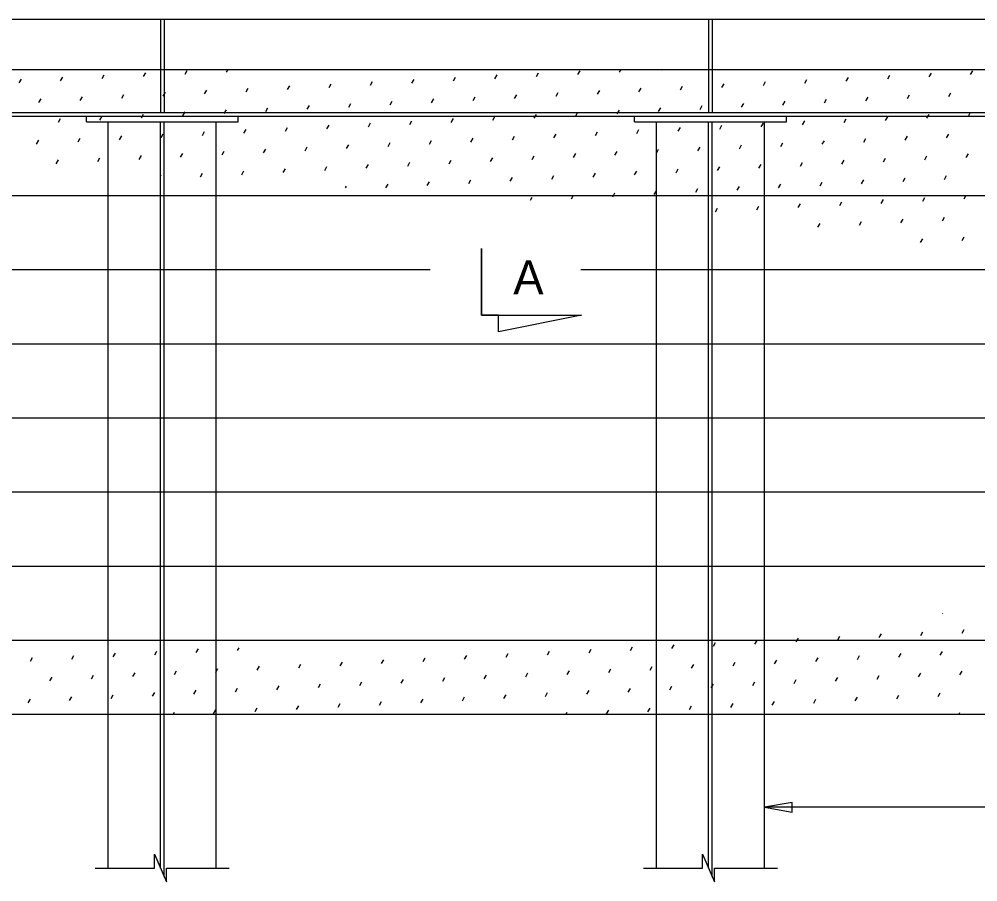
# Model space of a CAD drawing. Extents: x 0 to 61.6, y 0 to 38.9.
# Drawn here: x 30.2 to 40.98, y 14.06 to 23.77 of the extents above; entities that cross this region are included whole.
import ezdxf

# ---------------------------------------------------------------- set-up
doc = ezdxf.new("R2010")
doc.units = 0
for name, color, linetype in [('Dimension', 7, 'Continuous'), ('GroundLines', 7, 'Continuous'), ('SteelMisc', 7, 'Continuous'), ('SteelMisc_h', 7, 'Continuous'), ('Symbols', 7, 'Continuous'), ('TextStructures', 7, 'Continuous'), ('Wood', 7, 'Continuous'), ('Wood_h', 7, 'Continuous')]:
    doc.layers.add(name, color=color, linetype=linetype)

msp = doc.modelspace()

# ---------------------------------------------------------------- linework, layer by layer
at = {"layer": 'Dimension'}
for p, q in [((32.064, 23.148), (32.089, 23.19)), ((32.531, 23.172), (32.549, 23.203)), ((32.997, 23.197), (33.001, 23.203)), ((36.483, 23.146), (36.508, 23.188)), ((36.95, 23.171), (36.969, 23.203)), ((37.416, 23.195), (37.421, 23.203)), ((30.198, 23.051), (30.223, 23.093)), ((30.665, 23.075), (30.689, 23.117)), ((31.131, 23.099), (31.156, 23.141)), ((31.598, 23.124), (31.622, 23.166)), ((34.617, 23.049), (34.642, 23.091)), ((35.084, 23.073), (35.108, 23.115)), ((35.55, 23.098), (35.575, 23.14)), ((36.017, 23.122), (36.041, 23.164)), ((39.036, 23.047), (39.061, 23.089)), ((39.503, 23.071), (39.527, 23.113)), ((39.969, 23.096), (39.994, 23.138)), ((40.436, 23.12), (40.46, 23.162)), ((40.902, 23.144), (40.927, 23.186)), ((32.752, 22.951), (32.776, 22.993)), ((33.218, 22.976), (33.242, 23.018)), ((33.685, 23), (33.709, 23.042)), ((34.151, 23.024), (34.175, 23.066)), ((37.171, 22.95), (37.195, 22.992)), ((37.637, 22.974), (37.661, 23.016)), ((38.104, 22.998), (38.128, 23.04)), ((38.57, 23.023), (38.594, 23.065)), ((30.419, 22.83), (30.444, 22.872)), ((30.886, 22.854), (30.91, 22.896)), ((31.352, 22.878), (31.377, 22.92)), ((31.819, 22.903), (31.843, 22.945)), ((32.285, 22.927), (32.31, 22.969)), ((34.838, 22.828), (34.863, 22.87)), ((35.305, 22.852), (35.329, 22.894)), ((35.771, 22.876), (35.796, 22.918)), ((36.238, 22.901), (36.262, 22.943)), ((36.704, 22.925), (36.729, 22.967)), ((39.257, 22.826), (39.282, 22.868)), ((39.724, 22.85), (39.748, 22.892)), ((40.19, 22.875), (40.215, 22.917)), ((40.657, 22.899), (40.681, 22.941)), ((32.973, 22.73), (32.997, 22.772)), ((33.439, 22.755), (33.463, 22.797)), ((33.906, 22.779), (33.93, 22.821)), ((34.372, 22.803), (34.396, 22.845)), ((37.392, 22.729), (37.416, 22.771)), ((37.858, 22.753), (37.882, 22.795)), ((38.325, 22.777), (38.349, 22.819)), ((38.791, 22.802), (38.815, 22.844)), ((30.641, 22.609), (30.665, 22.651)), ((31.107, 22.633), (31.131, 22.675)), ((31.573, 22.657), (31.598, 22.699)), ((32.04, 22.682), (32.064, 22.724)), ((32.506, 22.706), (32.531, 22.748)), ((35.06, 22.607), (35.084, 22.649)), ((35.526, 22.631), (35.55, 22.673)), ((35.992, 22.655), (36.017, 22.697)), ((36.459, 22.68), (36.483, 22.722)), ((36.925, 22.704), (36.95, 22.746)), ((39.945, 22.629), (39.969, 22.671)), ((40.411, 22.654), (40.436, 22.696)), ((40.878, 22.678), (40.902, 22.72)), ((33.194, 22.509), (33.218, 22.551)), ((33.66, 22.534), (33.685, 22.576)), ((34.127, 22.558), (34.151, 22.6)), ((34.593, 22.582), (34.617, 22.624)), ((37.613, 22.507), (37.637, 22.549)), ((38.079, 22.532), (38.104, 22.574)), ((38.546, 22.556), (38.57, 22.598)), ((39.012, 22.581), (39.036, 22.623)), ((39.479, 22.605), (39.503, 22.647)), ((31.328, 22.412), (31.352, 22.454)), ((31.794, 22.436), (31.819, 22.478)), ((32.261, 22.461), (32.285, 22.503)), ((32.727, 22.485), (32.752, 22.527)), ((35.747, 22.41), (35.771, 22.452)), ((36.213, 22.434), (36.238, 22.476)), ((36.68, 22.459), (36.704, 22.501)), ((37.146, 22.483), (37.171, 22.525)), ((40.166, 22.408), (40.19, 22.45)), ((40.632, 22.433), (40.657, 22.475)), ((30.395, 22.363), (30.419, 22.405)), ((30.862, 22.387), (30.886, 22.429)), ((33.415, 22.288), (33.439, 22.33)), ((33.881, 22.313), (33.906, 22.355)), ((34.348, 22.337), (34.372, 22.379)), ((34.814, 22.361), (34.838, 22.403)), ((35.281, 22.386), (35.305, 22.428)), ((37.834, 22.286), (37.858, 22.328)), ((38.3, 22.311), (38.325, 22.353)), ((38.767, 22.335), (38.791, 22.377)), ((39.233, 22.36), (39.257, 22.401)), ((39.7, 22.384), (39.724, 22.426)), ((31.549, 22.191), (31.573, 22.233)), ((32.015, 22.215), (32.04, 22.257)), ((32.482, 22.24), (32.506, 22.282)), ((32.948, 22.264), (32.973, 22.306)), ((35.968, 22.189), (35.992, 22.231)), ((36.434, 22.213), (36.459, 22.255)), ((36.901, 22.238), (36.925, 22.28)), ((37.367, 22.262), (37.392, 22.304)), ((40.387, 22.187), (40.411, 22.229)), ((40.853, 22.212), (40.878, 22.254)), ((30.616, 22.142), (30.64, 22.184)), ((31.083, 22.166), (31.107, 22.208)), ((33.636, 22.067), (33.66, 22.109)), ((34.102, 22.092), (34.127, 22.134)), ((34.569, 22.116), (34.593, 22.158)), ((35.035, 22.14), (35.059, 22.182)), ((35.502, 22.165), (35.526, 22.207)), ((38.521, 22.09), (38.546, 22.132)), ((38.988, 22.114), (39.012, 22.156)), ((39.454, 22.138), (39.478, 22.18)), ((39.921, 22.163), (39.945, 22.205)), ((31.792, 22.008), (31.794, 22.012)), ((32.237, 21.994), (32.261, 22.036)), ((32.703, 22.018), (32.727, 22.06)), ((33.169, 22.043), (33.194, 22.085)), ((36.189, 21.968), (36.213, 22.01)), ((36.656, 21.992), (36.68, 22.034)), ((37.122, 22.017), (37.146, 22.059)), ((37.588, 22.041), (37.613, 22.083)), ((38.055, 22.065), (38.079, 22.107)), ((40.608, 21.966), (40.632, 22.008)), ((34.323, 21.871), (34.348, 21.913)), ((34.79, 21.895), (34.814, 21.937)), ((35.256, 21.919), (35.281, 21.961)), ((35.723, 21.944), (35.747, 21.986)), ((38.742, 21.869), (38.767, 21.911)), ((39.209, 21.893), (39.233, 21.935)), ((39.675, 21.917), (39.7, 21.959)), ((40.142, 21.942), (40.166, 21.984)), ((33.871, 21.87), (33.881, 21.888)), ((36.41, 21.747), (36.434, 21.789)), ((36.877, 21.771), (36.901, 21.813)), ((37.343, 21.796), (37.367, 21.838)), ((37.809, 21.82), (37.834, 21.862)), ((38.276, 21.844), (38.3, 21.886)), ((40.829, 21.745), (40.853, 21.787)), ((35.949, 21.732), (35.968, 21.765)), ((38.963, 21.648), (38.988, 21.69)), ((39.43, 21.672), (39.454, 21.714)), ((39.896, 21.696), (39.921, 21.738)), ((40.363, 21.721), (40.387, 21.763)), ((38.03, 21.599), (38.055, 21.641)), ((38.497, 21.623), (38.521, 21.665)), ((39.184, 21.427), (39.209, 21.469)), ((39.651, 21.451), (39.675, 21.493)), ((40.117, 21.475), (40.142, 21.517)), ((40.584, 21.5), (40.608, 21.542)), ((40.338, 21.254), (40.363, 21.296)), ((40.805, 21.279), (40.829, 21.321)), ((40.586, 17.081), (40.588, 17.086)), ((39.407, 16.787), (39.432, 16.829)), ((39.874, 16.811), (39.898, 16.853)), ((40.34, 16.835), (40.364, 16.877)), ((40.807, 16.86), (40.831, 16.902)), ((37.541, 16.689), (37.566, 16.731)), ((38.008, 16.714), (38.032, 16.756)), ((38.474, 16.738), (38.499, 16.78)), ((38.941, 16.762), (38.965, 16.804)), ((30.79, 16.569), (30.815, 16.611)), ((31.257, 16.594), (31.281, 16.636)), ((31.723, 16.618), (31.747, 16.66)), ((32.19, 16.642), (32.214, 16.684)), ((32.656, 16.667), (32.673, 16.697)), ((35.209, 16.567), (35.234, 16.609)), ((35.676, 16.592), (35.7, 16.634)), ((36.142, 16.616), (36.166, 16.658)), ((36.609, 16.64), (36.633, 16.682)), ((37.075, 16.665), (37.099, 16.707)), ((40.095, 16.59), (40.119, 16.632)), ((40.561, 16.614), (40.585, 16.656)), ((30.324, 16.545), (30.348, 16.587)), ((33.344, 16.47), (33.368, 16.512)), ((33.81, 16.494), (33.834, 16.536)), ((34.276, 16.519), (34.301, 16.561)), ((34.743, 16.543), (34.767, 16.585)), ((37.763, 16.468), (37.787, 16.51)), ((38.229, 16.492), (38.253, 16.534)), ((38.695, 16.517), (38.72, 16.559)), ((39.162, 16.541), (39.186, 16.583)), ((39.628, 16.566), (39.653, 16.608)), ((31.478, 16.372), (31.502, 16.414)), ((31.944, 16.397), (31.969, 16.439)), ((32.411, 16.421), (32.435, 16.463)), ((32.877, 16.446), (32.901, 16.488)), ((35.897, 16.371), (35.921, 16.413)), ((36.363, 16.395), (36.388, 16.437)), ((36.83, 16.419), (36.854, 16.461)), ((37.296, 16.444), (37.32, 16.486)), ((40.316, 16.369), (40.34, 16.411)), ((40.782, 16.393), (40.807, 16.435)), ((30.545, 16.324), (30.569, 16.366)), ((31.011, 16.348), (31.036, 16.39)), ((33.565, 16.249), (33.589, 16.291)), ((34.031, 16.273), (34.055, 16.315)), ((34.497, 16.298), (34.522, 16.34)), ((34.964, 16.322), (34.988, 16.364)), ((35.43, 16.346), (35.455, 16.388)), ((37.984, 16.247), (38.008, 16.289)), ((38.45, 16.271), (38.474, 16.313)), ((38.916, 16.296), (38.941, 16.338)), ((39.383, 16.32), (39.407, 16.362)), ((39.849, 16.345), (39.874, 16.386)), ((31.699, 16.151), (31.723, 16.193)), ((32.165, 16.176), (32.19, 16.218)), ((32.632, 16.2), (32.656, 16.242)), ((33.098, 16.225), (33.122, 16.267)), ((36.118, 16.15), (36.142, 16.192)), ((36.584, 16.174), (36.609, 16.216)), ((37.051, 16.198), (37.075, 16.24)), ((37.517, 16.223), (37.541, 16.265)), ((40.537, 16.148), (40.561, 16.19)), ((30.299, 16.078), (30.324, 16.12)), ((30.766, 16.103), (30.79, 16.145)), ((31.232, 16.127), (31.257, 16.169)), ((33.786, 16.028), (33.81, 16.07)), ((34.252, 16.052), (34.276, 16.094)), ((34.718, 16.077), (34.743, 16.119)), ((35.185, 16.101), (35.209, 16.143)), ((35.651, 16.125), (35.676, 16.167)), ((38.671, 16.05), (38.695, 16.092)), ((39.137, 16.075), (39.162, 16.117)), ((39.604, 16.099), (39.628, 16.141)), ((40.07, 16.123), (40.095, 16.165)), ((31.929, 15.947), (31.944, 15.972)), ((32.386, 15.955), (32.411, 15.997)), ((32.853, 15.979), (32.877, 16.021)), ((33.319, 16.003), (33.343, 16.045)), ((36.349, 15.947), (36.363, 15.971)), ((36.805, 15.953), (36.83, 15.995)), ((37.272, 15.977), (37.296, 16.019)), ((37.738, 16.002), (37.762, 16.044)), ((38.205, 16.026), (38.229, 16.068)), ((40.769, 15.947), (40.782, 15.969)), ((31.477, 15.947), (31.478, 15.948)), ((45.448, 14.902), (38.583, 14.902))]:
    msp.add_line(p, q, dxfattribs=at)
msp.add_lwpolyline([(38.583, 14.902), (38.895, 14.849), (38.895, 14.955)], close=True, dxfattribs=at)
at = {"layer": 'GroundLines'}
msp.add_line((4.623, 17.613), (45.665, 17.613), dxfattribs=at)
at = {"layer": 'SteelMisc'}
for p, q in [((6.534, 23.768), (44.75, 23.768)), ((31.791, 22.712), (31.791, 23.768)), ((31.832, 22.712), (31.832, 23.768)), ((37.958, 22.712), (37.958, 23.768)), ((37.999, 22.712), (37.999, 23.768)), ((6.288, 22.676), (44.996, 22.676)), ((6.534, 22.718), (44.75, 22.718)), ((30.954, 22.613), (30.954, 22.676)), ((32.663, 22.613), (32.663, 22.676)), ((37.121, 22.613), (37.121, 22.676)), ((38.83, 22.613), (38.83, 22.676)), ((30.954, 22.613), (32.663, 22.613)), ((31.201, 17.613), (31.201, 22.613)), ((32.416, 17.613), (32.416, 22.613)), ((37.121, 22.613), (38.83, 22.613)), ((37.368, 17.613), (37.368, 22.613)), ((38.583, 17.613), (38.583, 22.613))]:
    msp.add_line(p, q, dxfattribs=at)
at = {"layer": 'SteelMisc_h'}
for p, q in [((31.788, 14.219), (31.788, 22.613)), ((31.83, 14.122), (31.83, 22.613)), ((37.954, 14.219), (37.954, 22.613)), ((37.996, 14.122), (37.996, 22.613)), ((31.201, 14.219), (31.201, 17.613)), ((32.416, 14.219), (32.416, 17.613)), ((37.368, 14.219), (37.368, 17.613)), ((38.583, 14.219), (38.583, 17.613))]:
    msp.add_line(p, q, dxfattribs=at)
at = {"layer": 'Symbols'}
msp.add_lwpolyline([(35.401, 21.19), (35.401, 20.44), (36.526, 20.44), (35.589, 20.252), (35.589, 20.44), (35.401, 20.44)], close=True, dxfattribs=at)
for points in [[(31.055, 14.219), (31.72, 14.219), (31.72, 14.374), (31.855, 14.064), (31.855, 14.219), (32.561, 14.219)], [(37.222, 14.219), (37.887, 14.219), (37.887, 14.374), (38.022, 14.064), (38.022, 14.219), (38.728, 14.219)]]:
    msp.add_lwpolyline(points, dxfattribs=at)
at = {"layer": 'TextStructures'}
msp.add_line((6.534, 23.203), (44.786, 23.203), dxfattribs=at)
at = {"layer": 'Wood'}
for p, q in [((31.201, 21.78), (26.25, 21.78)), ((37.368, 21.78), (32.416, 21.78)), ((43.534, 21.78), (38.583, 21.78)), ((31.201, 20.947), (26.25, 20.947)), ((34.821, 20.947), (32.416, 20.947)), ((37.368, 20.947), (36.516, 20.947)), ((43.534, 20.947), (38.583, 20.947)), ((31.201, 20.113), (26.25, 20.113)), ((37.368, 20.113), (32.416, 20.113)), ((43.534, 20.113), (38.583, 20.113)), ((31.201, 19.28), (26.25, 19.28)), ((37.368, 19.28), (32.416, 19.28)), ((43.534, 19.28), (38.583, 19.28)), ((31.201, 18.447), (26.25, 18.447)), ((37.368, 18.447), (32.416, 18.447)), ((43.534, 18.447), (38.583, 18.447))]:
    msp.add_line(p, q, dxfattribs=at)
at = {"layer": 'Wood_h'}
for p, q in [((32.416, 21.78), (31.201, 21.78)), ((38.583, 21.78), (37.368, 21.78)), ((32.416, 20.947), (31.201, 20.947)), ((38.583, 20.947), (37.368, 20.947)), ((32.416, 20.113), (31.201, 20.113)), ((38.583, 20.113), (37.368, 20.113)), ((32.416, 19.28), (31.201, 19.28)), ((38.583, 19.28), (37.368, 19.28)), ((32.416, 18.447), (31.201, 18.447)), ((38.583, 18.447), (37.368, 18.447)), ((44.75, 16.78), (6.534, 16.78)), ((44.75, 15.947), (6.534, 15.947))]:
    msp.add_line(p, q, dxfattribs=at)

# ---------------------------------------------------------------- texts
at = {"layer": 'TextStructures'}
msp.add_text('A', height=0.384, dxfattribs=at).set_placement((35.756, 20.671))

doc.saveas('drawing.dxf')
